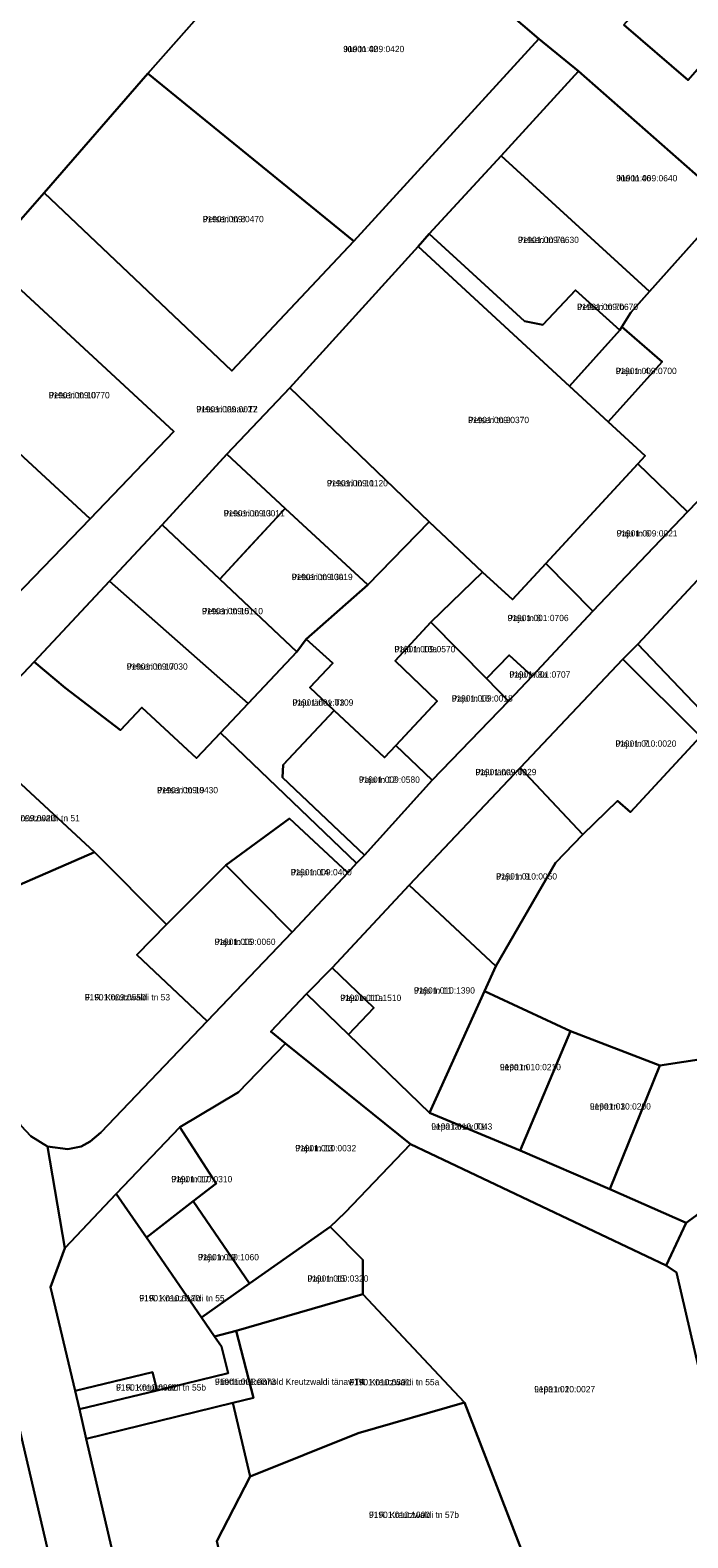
# Model space of a CAD drawing. Extents: x 675810 to 681273, y 6411190 to 6417565.
# Drawn here: x 678264 to 678420.5, y 6414897.2 to 6415256.1 of the extents above; entities that cross this region are included whole.
import ezdxf

# ---------------------------------------------------------------- set-up
doc = ezdxf.new("R2010")
doc.units = 0
for name, color, linetype in [('L_AADRESS', 7, 'Continuous'), ('PIIR', 7, 'Continuous'), ('TUNNUS', 7, 'Continuous')]:
    doc.layers.add(name, color=color, linetype=linetype)

msp = doc.modelspace()

# ---------------------------------------------------------------- linework, layer by layer
at = {"layer": 'PIIR'}
for points in [[(678286, 6415295.42), (678307.89, 6415320.24), (678311.89, 6415316.79), (678281.19, 6415282.24), (678297.38, 6415268.09), (678305.48, 6415261.06), (678291.98, 6415245.77), (678267.33, 6415217.4), (678261.23, 6415210.39), (678249.44, 6415220.06), (678203, 6415258.09), (678225.15, 6415284.07), (678228.71, 6415288.25), (678248, 6415310.9), (678261.57, 6415299.25), (678269.93, 6415309.22), (678270.63, 6415310.04)], [(678297.38, 6415268.09), (678327.36, 6415303.43), (678385.04, 6415254.07), (678340.98, 6415205.87), (678291.98, 6415245.77), (678305.48, 6415261.06)], [(678405.25, 6415257.4), (678433.25, 6415288.62), (678448.41, 6415276.29), (678439.58, 6415266.25), (678433.48, 6415259.07), (678420.55, 6415244.19)], [(678340.98, 6415205.87), (678312.02, 6415175.02), (678267.33, 6415217.4), (678291.98, 6415245.77)], [(678430.14, 6415214.96), (678411.38, 6415193.91), (678376.03, 6415226.17), (678394.49, 6415246.32)], [(678358.97, 6415207.61), (678376.03, 6415226.17), (678411.38, 6415193.91), (678406.92, 6415188.91), (678404.81, 6415185.53), (678404.29, 6415184.7), (678393.75, 6415194.21), (678385.95, 6415185.97), (678381.64, 6415186.86)], [(678461.97, 6415187.74), (678462.12, 6415184.59), (678420.41, 6415141.43), (678408.55, 6415152.84), (678410.33, 6415154.78), (678401.55, 6415162.87), (678414.34, 6415177.12), (678404.81, 6415185.53), (678406.92, 6415188.91), (678411.38, 6415193.91), (678430.14, 6415214.96)], [(678381.64, 6415186.86), (678385.95, 6415185.97), (678393.75, 6415194.21), (678404.29, 6415184.7), (678392.31, 6415171.4), (678356.33, 6415204.58), (678358.97, 6415207.61)], [(678356.33, 6415204.58), (678392.31, 6415171.4), (678401.55, 6415162.87), (678410.33, 6415154.78), (678408.55, 6415152.84), (678386.66, 6415129.12), (678378.75, 6415120.55), (678371.63, 6415127.11), (678358.95, 6415139.07), (678325.75, 6415170.99)], [(678239.06, 6415175.98), (678258.66, 6415197.14), (678298.17, 6415160.58), (678278.26, 6415139.8)], [(678392.31, 6415171.4), (678404.29, 6415184.7), (678404.81, 6415185.53), (678414.34, 6415177.12), (678401.55, 6415162.87)], [(678225.11, 6415161), (678239.06, 6415175.98), (678278.26, 6415139.8), (678258.25, 6415118.98), (678221.64, 6415152.67), (678225.29, 6415156.87), (678223.16, 6415158.94)], [(678344.36, 6415124.04), (678324.68, 6415142.28), (678310.82, 6415155.14), (678325.75, 6415170.99), (678358.95, 6415139.07)], [(678310.82, 6415155.14), (678324.68, 6415142.28), (678316.44, 6415133.35), (678309.13, 6415125.41), (678295.43, 6415138.32)], [(678408.55, 6415152.84), (678420.41, 6415141.43), (678397.88, 6415117.84), (678386.66, 6415129.12)], [(678324.68, 6415142.28), (678344.36, 6415124.04), (678329.68, 6415111.12), (678327.42, 6415108.12), (678309.13, 6415125.41)], [(678282.9, 6415124.98), (678295.43, 6415138.32), (678309.13, 6415125.41), (678327.42, 6415108.12), (678315.89, 6415095.84)], [(678344.36, 6415124.04), (678358.95, 6415139.07), (678371.63, 6415127.11), (678359.35, 6415115.2), (678350.82, 6415105.96), (678360.87, 6415096.35), (678350.97, 6415085.83), (678348.31, 6415083), (678336.31, 6415094.17), (678330.51, 6415099.62), (678335.99, 6415105.43), (678329.68, 6415111.12)], [(678408.56, 6415109.92), (678428.25, 6415131.04), (678448.65, 6415111.86), (678449.54, 6415103.08), (678426.73, 6415090.88)], [(678372.6, 6415101.74), (678359.35, 6415115.2), (678371.63, 6415127.11), (678378.75, 6415120.55), (678386.66, 6415129.12), (678397.88, 6415117.84), (678383.44, 6415102.34), (678378, 6415107.34)], [(678282.9, 6415124.98), (678315.89, 6415095.84), (678309.26, 6415088.81), (678303.55, 6415082.79), (678290.53, 6415094.9), (678285.52, 6415089.51), (678272.33, 6415099.55), (678264.97, 6415105.73)], [(678359.35, 6415115.2), (678372.6, 6415101.74), (678377.8, 6415096.4), (678359.66, 6415077.61), (678350.97, 6415085.83), (678360.87, 6415096.35), (678350.82, 6415105.96)], [(678341.61, 6415057.78), (678309.26, 6415088.81), (678315.89, 6415095.84), (678327.42, 6415108.12), (678329.68, 6415111.12), (678335.99, 6415105.43), (678330.51, 6415099.62), (678336.31, 6415094.17), (678324.19, 6415081.2), (678324.05, 6415078.21), (678343.55, 6415059.73)], [(678392.56, 6415017.82), (678372.11, 6415027.37), (678374.81, 6415033.31), (678388.99, 6415057.91), (678395.5, 6415064.65), (678403.78, 6415072.65), (678406.87, 6415069.96), (678423.48, 6415087.99), (678404.98, 6415106.41), (678408.56, 6415109.92), (678426.73, 6415090.88), (678449.54, 6415103.08), (678463.07, 6415057.11), (678454.26, 6415042.47), (678438.23, 6415026.81), (678434.07, 6415022.91), (678427.68, 6415012.64), (678425.23, 6415011.38), (678413.81, 6415009.65)], [(678248.8, 6415088.71), (678264.97, 6415105.73), (678272.33, 6415099.55), (678285.52, 6415089.51), (678290.53, 6415094.9), (678303.55, 6415082.79), (678309.26, 6415088.81), (678341.61, 6415057.78), (678339.56, 6415055.48), (678325.67, 6415068.43), (678310.56, 6415057.36), (678296.44, 6415043.18), (678279.3, 6415060.41)], [(678383.44, 6415102.34), (678377.8, 6415096.4), (678372.6, 6415101.74), (678378, 6415107.34)], [(678380.55, 6415080.49), (678404.98, 6415106.41), (678423.48, 6415087.99), (678406.87, 6415069.96), (678403.78, 6415072.65), (678395.5, 6415064.65)], [(678324.19, 6415081.2), (678336.31, 6415094.17), (678348.31, 6415083), (678350.97, 6415085.83), (678359.66, 6415077.61), (678343.55, 6415059.73), (678324.05, 6415078.21)], [(678248.8, 6415088.71), (678279.3, 6415060.41), (678247.9, 6415046.82), (678245.04, 6415058.45), (678235.88, 6415074.34)], [(678395.5, 6415064.65), (678388.99, 6415057.91), (678374.81, 6415033.31), (678354.21, 6415052.6), (678380.55, 6415080.49)], [(678326.37, 6415041.39), (678310.56, 6415057.36), (678325.67, 6415068.43), (678339.56, 6415055.48)], [(678279.3, 6415060.41), (678296.44, 6415043.18), (678289.38, 6415035.97), (678306.11, 6415020.2), (678280.79, 6414993.66), (678278.26, 6414991.56), (678276.16, 6414990.4), (678272.93, 6414989.72), (678268.13, 6414990.4), (678264.12, 6414992.85), (678261.88, 6414995.29), (678259.87, 6414998.84), (678259.01, 6415001.3), (678247.9, 6415046.82)], [(678310.56, 6415057.36), (678326.37, 6415041.39), (678306.11, 6415020.2), (678289.38, 6415035.97), (678296.44, 6415043.18)], [(678335.82, 6415032.93), (678354.21, 6415052.6), (678374.81, 6415033.31), (678372.11, 6415027.37), (678358.99, 6414998.41), (678339.76, 6415017.06), (678345.8, 6415023.34)], [(678329.73, 6415026.69), (678335.82, 6415032.93), (678345.8, 6415023.34), (678339.76, 6415017.06)], [(678329.73, 6415026.69), (678339.76, 6415017.06), (678358.99, 6414998.41), (678380.55, 6414989.41), (678401.96, 6414980.22), (678420.05, 6414972.18), (678415.33, 6414962.05), (678354.51, 6414990.92), (678324.72, 6415014.92), (678321.25, 6415017.73)], [(678392.56, 6415017.82), (678380.55, 6414989.41), (678358.99, 6414998.41), (678372.11, 6415027.37)], [(678401.96, 6414980.22), (678380.55, 6414989.41), (678392.56, 6415017.82), (678413.81, 6415009.65)], [(678324.72, 6415014.92), (678354.51, 6414990.92), (678347.59, 6414983.69), (678338.95, 6414974.66), (678335.38, 6414971.24), (678316.21, 6414957.79), (678302.78, 6414977.35), (678308.23, 6414981.56), (678299.64, 6414995), (678313.6, 6415003.33)], [(678420.05, 6414972.18), (678401.96, 6414980.22), (678413.81, 6415009.65), (678425.23, 6415011.38), (678442.05, 6414988.11)], [(678284.48, 6414979.07), (678299.64, 6414995), (678308.23, 6414981.56), (678302.78, 6414977.35), (678291.65, 6414968.67)], [(678354.51, 6414990.92), (678415.33, 6414962.05), (678417.78, 6414960.39), (678432.46, 6414897.13), (678385.96, 6414881.65), (678382.75, 6414889.63), (678367.32, 6414929.45), (678364.9, 6414932.05), (678343.14, 6414955.25), (678343.17, 6414963.4), (678335.38, 6414971.24), (678338.95, 6414974.66), (678347.59, 6414983.69)], [(678272.23, 6414966.2), (678284.48, 6414979.07), (678291.65, 6414968.67), (678304.75, 6414949.67), (678307.88, 6414945.15), (678309.51, 6414942.78), (678311.08, 6414936.44), (678294.21, 6414932.3), (678293.14, 6414936.66), (678274.72, 6414932.23), (678268.87, 6414956.87)], [(678304.75, 6414949.67), (678291.65, 6414968.67), (678302.78, 6414977.35), (678316.21, 6414957.79)], [(678313, 6414946.51), (678307.88, 6414945.15), (678304.75, 6414949.67), (678316.21, 6414957.79), (678335.38, 6414971.24), (678343.17, 6414963.4), (678343.14, 6414955.25)], [(678312.24, 6414929.33), (678317.13, 6414930.54), (678313, 6414946.51), (678343.14, 6414955.25), (678364.9, 6414932.05), (678367.32, 6414929.45), (678342.08, 6414922.11), (678316.36, 6414911.8)], [(678277.35, 6414920.74), (678275.74, 6414927.86), (678294.21, 6414932.3), (678311.08, 6414936.44), (678309.51, 6414942.78), (678307.88, 6414945.15), (678313, 6414946.51), (678317.13, 6414930.54), (678312.24, 6414929.33)], [(678274.72, 6414932.23), (678293.14, 6414936.66), (678294.21, 6414932.3), (678275.74, 6414927.86)], [(678312.24, 6414929.33), (678316.36, 6414911.8), (678308.39, 6414896.39), (678313.37, 6414875.13), (678324.76, 6414874.43), (678356, 6414882.13), (678356.78, 6414879.28), (678351.95, 6414877.79), (678353.7, 6414872.05), (678293, 6414853.41), (678277.35, 6414920.74)], [(678367.32, 6414929.45), (678382.75, 6414889.63), (678356, 6414882.13), (678324.76, 6414874.43), (678313.37, 6414875.13), (678308.39, 6414896.39), (678316.36, 6414911.8), (678342.08, 6414922.11)]]:
    msp.add_lwpolyline(points, close=True, dxfattribs=at)
for points in [[(678430.14, 6415214.96), (678394.49, 6415246.32), (678385.04, 6415254.07), (678327.36, 6415303.43)], [(678405.25, 6415257.4), (678420.55, 6415244.19)], [(678261.23, 6415210.39), (678267.33, 6415217.4), (678312.02, 6415175.02), (678340.98, 6415205.87), (678385.04, 6415254.07), (678394.49, 6415246.32), (678376.03, 6415226.17), (678358.97, 6415207.61), (678356.33, 6415204.58), (678325.75, 6415170.99), (678310.82, 6415155.14), (678295.43, 6415138.32), (678282.9, 6415124.98), (678264.97, 6415105.73), (678248.8, 6415088.71)], [(678258.25, 6415118.98), (678278.26, 6415139.8), (678298.17, 6415160.58), (678258.66, 6415197.14)], [(678428.25, 6415131.04), (678408.56, 6415109.92), (678404.98, 6415106.41), (678380.55, 6415080.49), (678354.21, 6415052.6), (678335.82, 6415032.93), (678329.73, 6415026.69), (678321.25, 6415017.73), (678324.72, 6415014.92), (678313.6, 6415003.33), (678299.64, 6414995), (678284.48, 6414979.07), (678272.23, 6414966.2), (678268.13, 6414990.4), (678272.93, 6414989.72), (678276.16, 6414990.4), (678278.26, 6414991.56), (678280.79, 6414993.66), (678306.11, 6415020.2), (678326.37, 6415041.39), (678339.56, 6415055.48), (678341.61, 6415057.78), (678343.55, 6415059.73), (678359.66, 6415077.61), (678377.8, 6415096.4), (678383.44, 6415102.34), (678397.88, 6415117.84), (678420.41, 6415141.43), (678462.12, 6415184.59)], [(678432.46, 6414897.13), (678417.78, 6414960.39), (678415.33, 6414962.05), (678420.05, 6414972.18), (678442.05, 6414988.11), (678463.49, 6415003.25), (678468.06, 6415006.53), (678475.79, 6415012.25), (678491.76, 6415023.99), (678515.55, 6415040.95), (678520.02, 6415024.94), (678496.43, 6415008.17), (678470.05, 6414989.05), (678454.33, 6414977.28), (678431.1, 6414960.63), (678437.67, 6414933.19), (678442.1, 6414914.71), (678446.71, 6414896.28)], [(678261.88, 6414995.29), (678264.12, 6414992.85), (678268.13, 6414990.4), (678272.23, 6414966.2), (678268.87, 6414956.87), (678274.72, 6414932.23), (678275.74, 6414927.86), (678277.35, 6414920.74), (678293, 6414853.41)], [(678057.96, 6414895.98), (678070.27, 6414908.75), (678073.04, 6414911.8), (678083.91, 6414910.27), (678090.83, 6414909.3), (678123, 6414901.96), (678187.43, 6414897.28), (678198.38, 6414897.86), (678207.47, 6414901.85), (678246.38, 6414945.52), (678250.14, 6414949.54), (678252.73, 6414949.61), (678256.56, 6414945.14), (678261.12, 6414924.5), (678331.34, 6414623.63)], [(678331.34, 6414623.63), (678261.12, 6414924.5)]]:
    msp.add_lwpolyline(points, dxfattribs=at)

# ---------------------------------------------------------------- texts
at = {"layer": 'L_AADRESS'}
for s, p in [('Jüri tn 42', (678338.51, 6415250.88)), ('Jüri tn 46', (678403.47, 6415220.12)), ('Petseri tn 8', (678305.07, 6415210.4)), ('Petseri tn 7a', (678380.05, 6415205.44)), ('Petseri tn 7b', (678394.13, 6415189.5)), ('Paju tn 4', (678403.33, 6415174.24)), ('Petseri tn 10', (678268.42, 6415168.47)), ('Petseri tänav T2', (678303.54, 6415165.12)), ('Petseri tn 9', (678368.2, 6415162.57)), ('Petseri tn 11', (678334.6, 6415147.51)), ('Petseri tn 13', (678310.05, 6415140.36)), ('Paju tn 6', (678403.53, 6415135.58)), ('Petseri tn 13a', (678326.23, 6415125.2)), ('Petseri tn 15', (678304.89, 6415117.08)), ('Paju tn 8', (678377.61, 6415115.43)), ('Paju tn 10a', (678350.66, 6415108.01)), ('Petseri tn 17', (678286.97, 6415103.88)), ('Paju tn 8a', (678378.02, 6415101.98)), ('Paju tn 10', (678364.31, 6415096.29)), ('Paju tänav T3', (678326.4, 6415095.3)), ('Paju tn 7', (678403.26, 6415085.53)), ('Paju tänav T1', (678369.95, 6415078.76)), ('Petseri tn 19', (678294.19, 6415074.46)), ('Paju tn 12', (678342.22, 6415076.95)), ('F. R. Kreutzwaldi tn 51', (678255.52, 6415067.77)), ('Paju tn 14', (678326.01, 6415054.91)), ('Paju tn 9', (678374.86, 6415053.92)), ('Paju tn 16', (678307.88, 6415038.35)), ('F. R. Kreutzwaldi tn 53', (678277, 6415025.14)), ('Paju tn 11a', (678337.79, 6415024.99)), ('Paju tn 11', (678355.32, 6415026.77)), ('Lepa tn 1', (678375.78, 6415008.53)), ('Lepa tn 3', (678397.18, 6414999.16)), ('Lepa tänav T1', (678359.45, 6414994.37)), ('Paju tn 13', (678327.07, 6414989.22)), ('Paju tn 17', (678297.58, 6414981.84)), ('Paju tn 19', (678303.93, 6414963.27)), ('Paju tn 15', (678329.97, 6414958.19)), ('F. R. Kreutzwaldi tn 55', (678289.97, 6414953.5)), ('F. R. Kreutzwaldi tn 55b', (678284.44, 6414932.26)), ('Friedrich Reinhold Kreutzwaldi tänav T4', (678307.97, 6414933.62)), ('F. R. Kreutzwaldi tn 55a', (678339.94, 6414933.53)), ('Lepa tn 2', (678383.92, 6414931.84)), ('F. R. Kreutzwaldi tn 57b', (678344.62, 6414901.94))]:
    msp.add_text(s, height=1.5, dxfattribs=at).set_placement(p)
at = {"layer": 'TUNNUS'}
for s, p in [('91901:009:0420', (678338.51, 6415250.88)), ('91901:009:0640', (678403.47, 6415220.12)), ('91901:009:0470', (678305.07, 6415210.4)), ('91901:009:0630', (678380.05, 6415205.44)), ('91901:009:0670', (678394.13, 6415189.5)), ('91901:009:0700', (678403.33, 6415174.24)), ('91901:009:0770', (678268.42, 6415168.47)), ('91901:009:0027', (678303.54, 6415165.12)), ('91901:009:0370', (678368.2, 6415162.57)), ('91901:009:0120', (678334.6, 6415147.51)), ('91901:009:0011', (678310.05, 6415140.36)), ('91901:009:0021', (678403.53, 6415135.58)), ('91901:009:0019', (678326.23, 6415125.2)), ('91901:009:0110', (678304.89, 6415117.08)), ('91901:001:0706', (678377.61, 6415115.43)), ('91901:009:0570', (678350.66, 6415108.01)), ('91901:009:0030', (678286.97, 6415103.88)), ('91901:001:0707', (678378.02, 6415101.98)), ('91901:009:0018', (678364.31, 6415096.29)), ('91901:001:0109', (678326.4, 6415095.3)), ('91901:010:0020', (678403.26, 6415085.53)), ('91901:009:0029', (678369.95, 6415078.76)), ('91901:009:0580', (678342.22, 6415076.95)), ('91901:009:0430', (678294.19, 6415074.46)), ('91901:009:0020', (678255.52, 6415067.77)), ('91901:009:0400', (678326.01, 6415054.91)), ('91901:010:0050', (678374.86, 6415053.92)), ('91901:009:0060', (678307.88, 6415038.35)), ('91901:009:0550', (678277, 6415025.14)), ('91901:010:1510', (678337.79, 6415024.99)), ('91901:010:1390', (678355.32, 6415026.77)), ('91901:010:0210', (678375.78, 6415008.53)), ('91901:010:0200', (678397.18, 6414999.16)), ('91901:010:0043', (678359.45, 6414994.37)), ('91901:010:0032', (678327.07, 6414989.22)), ('91901:010:0310', (678297.58, 6414981.84)), ('91901:010:1060', (678303.93, 6414963.27)), ('91901:010:0320', (678329.97, 6414958.19)), ('91901:010:0170', (678289.97, 6414953.5)), ('91901:010:0302', (678284.44, 6414932.26)), ('91901:001:0373', (678307.97, 6414933.62)), ('91901:010:0301', (678339.94, 6414933.53)), ('91901:010:0027', (678383.92, 6414931.84)), ('91901:010:1000', (678344.62, 6414901.94))]:
    msp.add_text(s, height=1.5, dxfattribs=at).set_placement(p)

doc.saveas('drawing.dxf')
